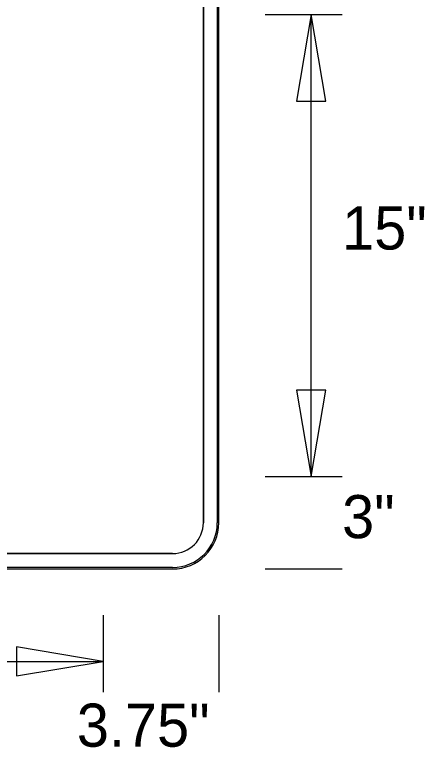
# Model space of a CAD drawing. Extents: x 0 to 770, y 0 to 495.
# Drawn here: x 169.4 to 202.6, y 38.1 to 97.6 of the extents above; entities that cross this region are included whole.
import ezdxf

# ---------------------------------------------------------------- set-up
doc = ezdxf.new("R2010")
doc.units = 0
for name, color, linetype in [('Dimension', 7, 'Continuous'), ('GSBWFill', 7, 'Continuous'), ('GSColorFill', 7, 'Continuous'), ('GSDims', 7, 'Continuous'), ('GSOutline', 7, 'Continuous')]:
    doc.layers.add(name, color=color, linetype=linetype)

msp = doc.modelspace()

# ---------------------------------------------------------------- linework, layer by layer
at = {"layer": 'Dimension'}
for points in [[(193.419, 97.623), (192.23, 90.606), (194.607, 90.606)], [(193.419, 60.123), (194.607, 67.139), (192.23, 67.139)], [(176.544, 45.123), (169.527, 46.311), (169.527, 43.934)]]:
    msp.add_lwpolyline(points, close=True, dxfattribs=at)
at = {"layer": 'GSBWFill'}
for p, q in [((184.669, 138.873), (184.669, 56.373)), ((185.919, 56.373), (185.919, 138.873)), ((182.169, 53.873), (114.681, 53.873)), ((114.681, 52.623), (182.169, 52.623))]:
    msp.add_line(p, q, dxfattribs=at)
for radius in [3.75, 2.5]:
    msp.add_arc((182.169, 56.373), radius, 270, 0, dxfattribs=at)
at = {"layer": 'GSColorFill'}
for p, q in [((184.669, 138.873), (184.669, 56.373)), ((185.794, 138.873), (185.794, 56.373)), ((185.919, 56.373), (185.919, 138.873)), ((185.919, 56.373), (185.919, 138.873)), ((185.919, 56.373), (185.919, 138.873)), ((182.169, 53.873), (114.681, 53.873)), ((114.669, 52.623), (182.169, 52.623)), ((182.169, 52.748), (114.67, 52.748)), ((114.67, 52.623), (182.169, 52.623)), ((114.681, 52.623), (182.169, 52.623))]:
    msp.add_line(p, q, dxfattribs=at)
for radius in [3.75, 3.75, 2.5, 3.75, 3.625]:
    msp.add_arc((182.169, 56.373), radius, 270, 0, dxfattribs=at)
at = {"layer": 'GSDims'}
for p, q in [((189.669, 97.623), (195.919, 97.623)), ((193.419, 60.123), (193.419, 97.623)), ((189.669, 60.123), (195.919, 60.123)), ((189.669, 60.123), (195.919, 60.123)), ((189.669, 52.623), (195.919, 52.623)), ((176.544, 48.873), (176.544, 42.623)), ((176.544, 48.873), (176.544, 42.623)), ((185.919, 48.873), (185.919, 42.623)), ((120.294, 45.123), (176.544, 45.123))]:
    msp.add_line(p, q, dxfattribs=at)
at = {"layer": 'GSOutline'}
for p, q in [((184.669, 56.373), (184.669, 138.873)), ((185.919, 56.373), (185.919, 138.873)), ((114.669, 53.873), (182.169, 53.873)), ((114.669, 52.623), (182.169, 52.623))]:
    msp.add_line(p, q, dxfattribs=at)
for radius in [3.75, 2.5]:
    msp.add_arc((182.169, 56.373), radius, 270, 0, dxfattribs=at)

# ---------------------------------------------------------------- texts
at = {"layer": 'GSDims'}
for s, p in [('15"', (195.919, 78.554)), ('3"', (195.919, 55.122)), ('3.75"', (174.407, 38.192))]:
    msp.add_text(s, height=3.5, dxfattribs=at).set_placement(p)

doc.saveas('drawing.dxf')
